// Mitsubishi GX Works2 project: LM2500_ExtControl_Ex1_cont   PLC: Q03UDV

// global labels: Global1
VAR_GLOBAL
  FILE_No AT D10 : INT;
END_VAR

PROGRAM MAIN
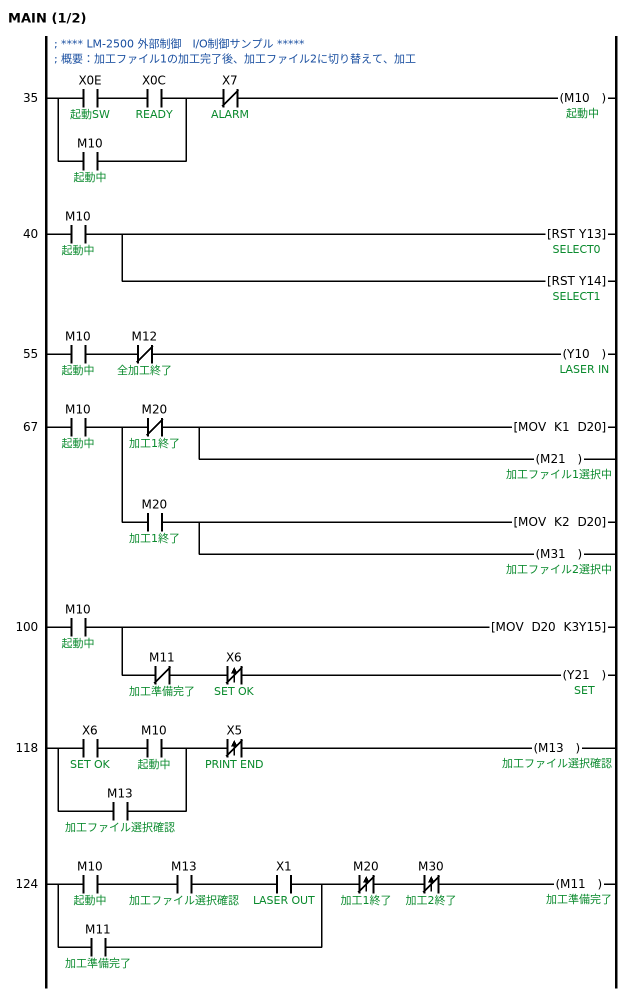
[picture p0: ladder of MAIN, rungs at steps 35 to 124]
; **** LM-2500 外部制御　I/O制御サンプル *****
; 概要：加工ファイル1の加工完了後、加工ファイル2に切り替えて、加工
35    LD      X0E  ; 起動SW
      AND     X0C  ; READY
      OR      M10  ; 起動中
      ANI     X7  ; ALARM
      OUT     M10  ; 起動中
40    LD      M10  ; 起動中
      RST     Y13  ; SELECT0
        [note] ファイル番号セレクト
      RST     Y14  ; SELECT1
55    LD      M10  ; 起動中
      ANI     M12  ; 全加工終了
      OUT     Y10  ; LASER IN
        [note] レーザー励起ON
67    LD      M10  ; 起動中
      MPS
      ANI     M20  ; 加工1終了
      MOV     K1 D20
        [note] 加工ファイル1指定
      OUT     M21  ; 加工ファイル1選択中
      MPP
      AND     M20  ; 加工1終了
      MOV     K2 D20
        [note] 加工ファイル2指定
      OUT     M31  ; 加工ファイル2選択中
100   LD      M10  ; 起動中
      MOV     D20 K3Y15  ; D0
        [note] ファイル番号指定
      ANI     M11  ; 加工準備完了
      ANDPI   X6  ; SET OK
      OUT     Y21  ; SET
118   LD      X6  ; SET OK
      AND     M10  ; 起動中
      OR      M13  ; 加工ファイル選択確認
      ANDPI   X5  ; PRINT END
      OUT     M13  ; 加工ファイル選択確認
124   LD      M10  ; 起動中
      AND     M13  ; 加工ファイル選択確認
      AND     X1  ; LASER OUT
      OR      M11  ; 加工準備完了
      ANDPI   M20  ; 加工1終了
      ANDPI   M30  ; 加工2終了
      OUT     M11  ; 加工準備完了
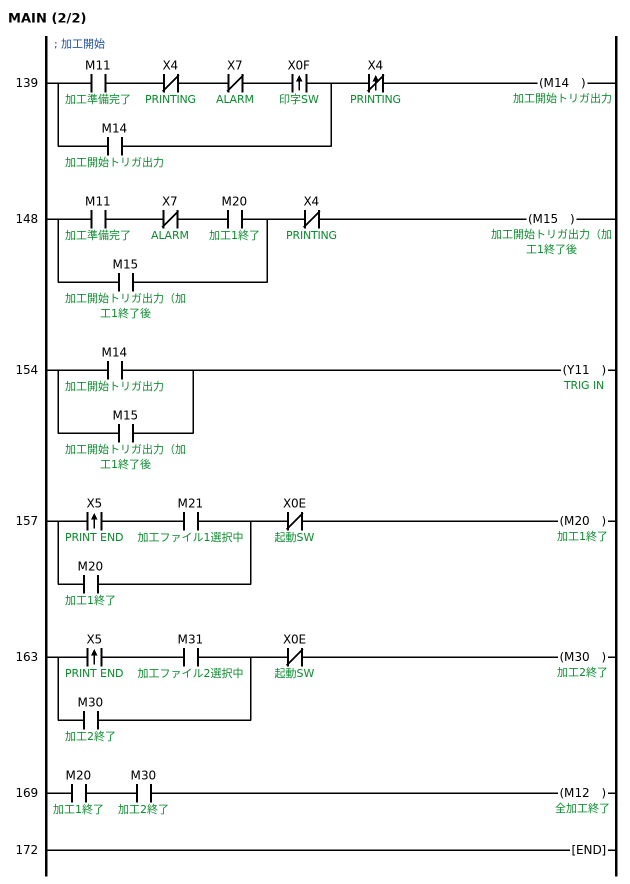
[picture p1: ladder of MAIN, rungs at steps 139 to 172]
; 加工開始
139   LD      M11  ; 加工準備完了
      ANI     X4  ; PRINTING
      ANI     X7  ; ALARM
      ANDP    X0F  ; 印字SW
      OR      M14  ; 加工開始トリガ出力
      ANDPI   X4  ; PRINTING
      OUT     M14  ; 加工開始トリガ出力
148   LD      M11  ; 加工準備完了
      ANI     X7  ; ALARM
      AND     M20  ; 加工1終了
      OR      M15  ; 加工開始トリガ出力（加工1終了後
      ANI     X4  ; PRINTING
      OUT     M15  ; 加工開始トリガ出力（加工1終了後
154   LD      M14  ; 加工開始トリガ出力
      OR      M15  ; 加工開始トリガ出力（加工1終了後
      OUT     Y11  ; TRIG IN
157   LDP     X5  ; PRINT END
      AND     M21  ; 加工ファイル1選択中
      OR      M20  ; 加工1終了
      ANI     X0E  ; 起動SW
      OUT     M20  ; 加工1終了
163   LDP     X5  ; PRINT END
      AND     M31  ; 加工ファイル2選択中
      OR      M30  ; 加工2終了
      ANI     X0E  ; 起動SW
      OUT     M30  ; 加工2終了
169   LD      M20  ; 加工1終了
      AND     M30  ; 加工2終了
      OUT     M12  ; 全加工終了
172   END
END_PROGRAM

// device comments not shown above
X0  ; CONT MODE OUT
X2  ; SHUTTER OUT
X3  ; PRINT READY
X8  ; CEND0
X9  ; CEND1
X0A  ; CEND2
X0B  ; CEND3
Y12  ; ALARM RST
Y16  ; D1
Y17  ; D2
Y18  ; D3
Y19  ; D4
Y1A  ; D5
Y1B  ; D6
Y1C  ; D7
Y1D  ; D8
Y1E  ; D9
Y1F  ; D予備1
Y20  ; D予備2
